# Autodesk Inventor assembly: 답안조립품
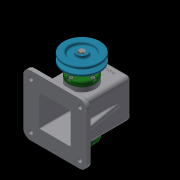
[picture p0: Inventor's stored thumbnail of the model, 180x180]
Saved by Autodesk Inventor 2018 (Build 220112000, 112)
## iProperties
Created: 2022-11
Part Number: 답안조립품
Material: 일반
Document SubType Name: Assembly
Designer: home
Author: home
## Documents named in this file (16)
- C:\Users\kimgi\Desktop\721106V1016\답안조립품.iam
- C:\Users\kimgi\Desktop\721106V1016\본체.ipt
- C:\Users\kimgi\Desktop\721106V1016\앞커버.ipt
- C:\Users\kimgi\Desktop\721106V1016\뒤커버.ipt
- C:\Users\kimgi\Desktop\721106V1016\편심축.ipt
- C:\Users\kimgi\Desktop\721106V1016\베어링 6201.ipt
- C:\Users\kimgi\Desktop\721106V1016\오일실 12 25 7.ipt
- C:\Users\kimgi\Desktop\721106V1016\V벨트풀리.ipt
- C:\Users\kimgi\Desktop\721106V1016\키 4 x 4 x 15.ipt
- C:\Users\kimgi\Desktop\721106V1016\멈춤나사 M3 x 8.ipt
- C:\Users\kimgi\Desktop\721106V1016\볼트 M4 x 12.ipt
- C:\Users\kimgi\Desktop\721106V1016\링크.ipt
- C:\Users\kimgi\Desktop\721106V1016\슬라이드.ipt
- C:\Users\kimgi\Desktop\721106V1016\핀 5 x 18.ipt
- C:\Users\kimgi\Desktop\721106V1016\고정핀 1.2 x 10.ipt
- C:\Users\kimgi\Desktop\721106V1016\부시.ipt
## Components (11 placed, 4 different names)
1. V벨트풀리:1
2. ISO 4762 M4 x 12:1
3. ISO 4762 M4 x 12:2
4. ISO 4762 M4 x 12:3
5. ISO 4762 M4 x 12:4
6. ISO 4762 M4 x 12:5
7. ISO 4762 M4 x 12:6
8. ISO 4762 M4 x 12:7
9. ISO 4762 M4 x 12:8
10. 핀 5 x 18:1
11. 고정핀 1.2 x 10:1
